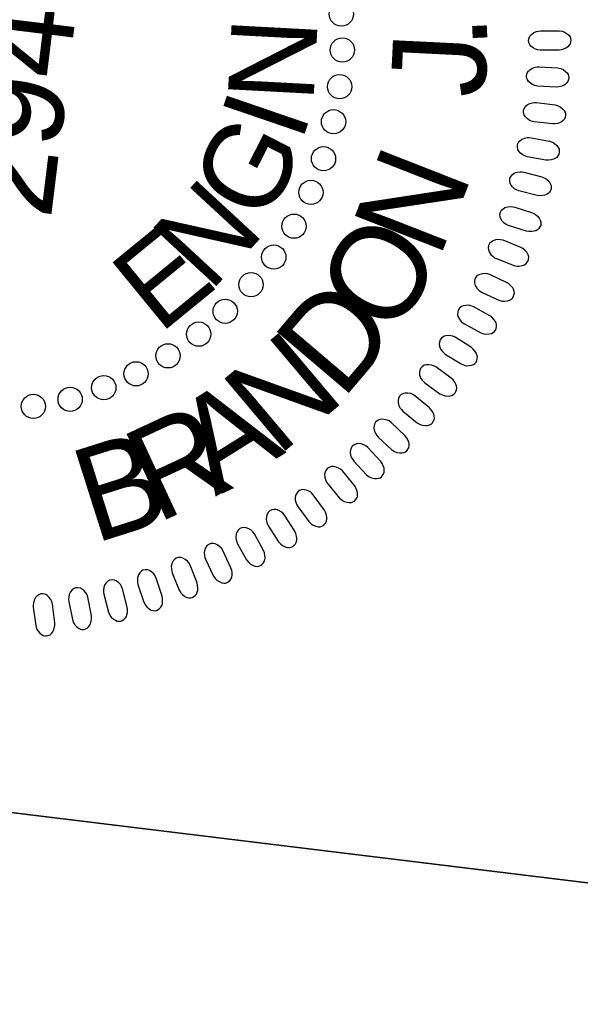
# Model space of a CAD drawing. Extents: x 480344 to 482186, y 488805 to 491553.
# Drawn here: x 480927.1 to 480964.2, y 490365.2 to 490429.6 of the extents above; entities that cross this region are included whole.
import ezdxf

# ---------------------------------------------------------------- set-up
doc = ezdxf.new("R2010")
doc.units = 0
for name, color, linetype in [('Sheet Layout Plan Border', 7, 'Continuous'), ('Sheet PE Seal Cell', 7, 'Continuous'), ('Sheet Plan CELL', 7, 'Continuous')]:
    doc.layers.add(name, color=color, linetype=linetype)

msp = doc.modelspace()

# ---------------------------------------------------------------- linework, layer by layer
at = {"layer": 'Sheet Layout Plan Border'}
msp.add_lwpolyline([(481703.226, 488995.253), (481861.691, 490292.688), (481782.266, 490302.389), (481802.944, 490471.693), (481574.795, 490460.718), (481089.788, 490519.955), (481007.711, 490529.98), (480988.134, 490369.7), (480815.851, 490390.73), (480660.971, 489122.552)], close=True, dxfattribs=at)
at = {"layer": 'Sheet PE Seal Cell'}
for points in [[(480961.54, 490428.859), (480962.767, 490428.864), (480962.986, 490428.827), (480963.127, 490428.776), (480963.297, 490428.664), (480963.407, 490428.567), (480963.487, 490428.455), (480963.527, 490428.351), (480963.547, 490428.239), (480963.528, 490428.127), (480963.499, 490428.007), (480963.439, 490427.902), (480963.34, 490427.797), (480963.26, 490427.737), (480963.11, 490427.669), (480962.931, 490427.608), (480962.772, 490427.586), (480961.515, 490427.573), (480961.346, 490427.595), (480961.206, 490427.64), (480961.046, 490427.729), (480960.906, 490427.84), (480960.826, 490427.937), (480960.765, 490428.094), (480960.745, 490428.244), (480960.785, 490428.393), (480960.834, 490428.498), (480960.933, 490428.625), (480961.102, 490428.745), (480961.282, 490428.813), (480961.411, 490428.843)], [(480961.446, 490426.487), (480962.671, 490426.415), (480962.888, 490426.365), (480963.024, 490426.305), (480963.187, 490426.182), (480963.291, 490426.079), (480963.363, 490425.962), (480963.397, 490425.856), (480963.41, 490425.742), (480963.383, 490425.632), (480963.346, 490425.514), (480963.281, 490425.413), (480963.175, 490425.314), (480963.092, 490425.26), (480962.938, 490425.201), (480962.756, 490425.152), (480962.595, 490425.139), (480961.34, 490425.206), (480961.172, 490425.238), (480961.036, 490425.292), (480960.882, 490425.391), (480960.749, 490425.51), (480960.675, 490425.612), (480960.624, 490425.772), (480960.614, 490425.923), (480960.662, 490426.07), (480960.718, 490426.171), (480960.825, 490426.292), (480961.002, 490426.402), (480961.185, 490426.458), (480961.316, 490426.481)], [(480961.28, 490424.123), (480962.498, 490423.974), (480962.711, 490423.91), (480962.844, 490423.841), (480962.998, 490423.709), (480963.096, 490423.599), (480963.161, 490423.478), (480963.188, 490423.37), (480963.194, 490423.256), (480963.161, 490423.147), (480963.116, 490423.032), (480963.045, 490422.935), (480962.932, 490422.844), (480962.846, 490422.794), (480962.689, 490422.745), (480962.504, 490422.708), (480962.343, 490422.705), (480961.095, 490422.85), (480960.929, 490422.893), (480960.796, 490422.955), (480960.648, 490423.063), (480960.524, 490423.191), (480960.456, 490423.298), (480960.416, 490423.461), (480960.414, 490423.612), (480960.472, 490423.755), (480960.534, 490423.853), (480960.648, 490423.968), (480960.831, 490424.065), (480961.018, 490424.11), (480961.15, 490424.123)], [(480960.924, 490421.796), (480962.13, 490421.57), (480962.338, 490421.493), (480962.466, 490421.417), (480962.613, 490421.275), (480962.703, 490421.16), (480962.76, 490421.035), (480962.781, 490420.924), (480962.779, 490420.81), (480962.739, 490420.704), (480962.688, 490420.592), (480962.61, 490420.5), (480962.492, 490420.416), (480962.403, 490420.371), (480962.243, 490420.333), (480962.056, 490420.307), (480961.895, 490420.314), (480960.659, 490420.537), (480960.496, 490420.591), (480960.367, 490420.661), (480960.227, 490420.778), (480960.11, 490420.913), (480960.049, 490421.024), (480960.019, 490421.189), (480960.028, 490421.34), (480960.094, 490421.48), (480960.162, 490421.573), (480960.283, 490421.68), (480960.472, 490421.766), (480960.662, 490421.8), (480960.794, 490421.805)], [(480960.447, 490419.52), (480961.636, 490419.219), (480961.84, 490419.129), (480961.963, 490419.044), (480962.1, 490418.894), (480962.182, 490418.773), (480962.232, 490418.644), (480962.245, 490418.533), (480962.236, 490418.419), (480962.19, 490418.316), (480962.132, 490418.207), (480962.048, 490418.12), (480961.925, 490418.044), (480961.833, 490418.005), (480961.672, 490417.977), (480961.483, 490417.962), (480961.323, 490417.98), (480960.103, 490418.28), (480959.945, 490418.344), (480959.82, 490418.422), (480959.687, 490418.547), (480959.579, 490418.69), (480959.526, 490418.804), (480959.506, 490418.971), (480959.524, 490419.121), (480959.599, 490419.256), (480959.673, 490419.345), (480959.8, 490419.444), (480959.994, 490419.518), (480960.185, 490419.54), (480960.318, 490419.537)], [(480959.836, 490417.21), (480961.005, 490416.836), (480961.202, 490416.733), (480961.319, 490416.641), (480961.447, 490416.482), (480961.521, 490416.356), (480961.563, 490416.225), (480961.569, 490416.113), (480961.553, 490416), (480961.5, 490415.9), (480961.435, 490415.795), (480961.346, 490415.714), (480961.22, 490415.645), (480961.125, 490415.612), (480960.962, 490415.593), (480960.773, 490415.591), (480960.614, 490415.619), (480959.416, 490415.995), (480959.261, 490416.069), (480959.142, 490416.154), (480959.017, 490416.288), (480958.918, 490416.437), (480958.872, 490416.554), (480958.863, 490416.722), (480958.89, 490416.871), (480958.974, 490417), (480959.053, 490417.085), (480959.186, 490417.176), (480959.384, 490417.237), (480959.576, 490417.247), (480959.708, 490417.236)], [(480958.628, 490413.81), (480959.77, 490413.363), (480959.987, 490413.318), (480960.137, 490413.315), (480960.336, 490413.358), (480960.473, 490413.408), (480960.588, 490413.484), (480960.664, 490413.566), (480960.723, 490413.664), (480960.745, 490413.775), (480960.761, 490413.898), (480960.744, 490414.017), (480960.689, 490414.15), (480960.637, 490414.235), (480960.522, 490414.352), (480960.376, 490414.474), (480960.236, 490414.553), (480959.069, 490415.018), (480958.902, 490415.059), (480958.756, 490415.068), (480958.575, 490415.042), (480958.404, 490414.989), (480958.294, 490414.927), (480958.181, 490414.803), (480958.108, 490414.671), (480958.091, 490414.517), (480958.099, 490414.402), (480958.145, 490414.247), (480958.26, 490414.074), (480958.403, 490413.946), (480958.512, 490413.871)], [(480957.677, 490411.576), (480958.789, 490411.058), (480959.004, 490410.999), (480959.152, 490410.987), (480959.353, 490411.017), (480959.494, 490411.059), (480959.614, 490411.128), (480959.693, 490411.205), (480959.759, 490411.298), (480959.788, 490411.408), (480959.812, 490411.53), (480959.802, 490411.65), (480959.755, 490411.787), (480959.708, 490411.874), (480959.601, 490411.999), (480959.464, 490412.128), (480959.329, 490412.217), (480958.193, 490412.754), (480958.029, 490412.805), (480957.884, 490412.823), (480957.702, 490412.809), (480957.528, 490412.767), (480957.414, 490412.712), (480957.294, 490412.596), (480957.212, 490412.468), (480957.185, 490412.316), (480957.187, 490412.2), (480957.223, 490412.043), (480957.326, 490411.863), (480957.461, 490411.726), (480957.566, 490411.644)], [(480956.513, 490409.493), (480957.591, 490408.906), (480957.801, 490408.834), (480957.949, 490408.812), (480958.152, 490408.83), (480958.294, 490408.863), (480958.418, 490408.924), (480958.503, 490408.996), (480958.575, 490409.085), (480958.61, 490409.193), (480958.641, 490409.313), (480958.64, 490409.433), (480958.601, 490409.572), (480958.56, 490409.663), (480958.461, 490409.794), (480958.332, 490409.932), (480958.203, 490410.029), (480957.102, 490410.636), (480956.943, 490410.698), (480956.799, 490410.724), (480956.616, 490410.722), (480956.44, 490410.691), (480956.323, 490410.643), (480956.195, 490410.534), (480956.106, 490410.412), (480956.07, 490410.262), (480956.064, 490410.146), (480956.09, 490409.987), (480956.182, 490409.801), (480956.308, 490409.656), (480956.407, 490409.568)], [(480955.255, 490407.503), (480956.293, 490406.85), (480956.499, 490406.765), (480956.644, 490406.734), (480956.848, 490406.739), (480956.993, 490406.763), (480957.12, 490406.815), (480957.209, 490406.882), (480957.286, 490406.967), (480957.328, 490407.073), (480957.367, 490407.19), (480957.372, 490407.31), (480957.343, 490407.452), (480957.308, 490407.545), (480957.217, 490407.682), (480957.097, 490407.828), (480956.974, 490407.932), (480955.914, 490408.608), (480955.758, 490408.679), (480955.617, 490408.715), (480955.434, 490408.725), (480955.256, 490408.704), (480955.137, 490408.664), (480955.003, 490408.563), (480954.906, 490408.447), (480954.86, 490408.299), (480954.847, 490408.184), (480954.863, 490408.023), (480954.943, 490407.832), (480955.06, 490407.679), (480955.153, 490407.585)], [(480953.907, 490405.593), (480954.902, 490404.876), (480955.102, 490404.778), (480955.246, 490404.738), (480955.449, 490404.73), (480955.595, 490404.745), (480955.725, 490404.789), (480955.819, 490404.851), (480955.9, 490404.931), (480955.949, 490405.033), (480955.995, 490405.147), (480956.008, 490405.267), (480955.988, 490405.41), (480955.959, 490405.505), (480955.876, 490405.648), (480955.766, 490405.801), (480955.649, 490405.913), (480954.634, 490406.653), (480954.484, 490406.734), (480954.344, 490406.779), (480954.162, 490406.8), (480953.984, 490406.791), (480953.862, 490406.759), (480953.722, 490406.666), (480953.618, 490406.556), (480953.563, 490406.412), (480953.542, 490406.298), (480953.549, 490406.137), (480953.617, 490405.941), (480953.723, 490405.781), (480953.81, 490405.681)], [(480952.455, 490403.738), (480953.404, 490402.959), (480953.597, 490402.849), (480953.738, 490402.8), (480953.941, 490402.779), (480954.087, 490402.785), (480954.219, 490402.821), (480954.317, 490402.876), (480954.403, 490402.951), (480954.459, 490403.05), (480954.512, 490403.161), (480954.532, 490403.28), (480954.521, 490403.424), (480954.498, 490403.522), (480954.425, 490403.668), (480954.324, 490403.828), (480954.215, 490403.947), (480953.248, 490404.75), (480953.103, 490404.84), (480952.967, 490404.894), (480952.786, 490404.926), (480952.607, 490404.928), (480952.484, 490404.903), (480952.338, 490404.821), (480952.228, 490404.717), (480952.164, 490404.576), (480952.136, 490404.463), (480952.132, 490404.302), (480952.187, 490404.103), (480952.284, 490403.936), (480952.365, 490403.831)], [(480950.822, 490402.021), (480951.72, 490401.185), (480951.906, 490401.063), (480952.044, 490401.006), (480952.244, 490400.972), (480952.391, 490400.968), (480952.526, 490400.996), (480952.626, 490401.045), (480952.717, 490401.114), (480952.779, 490401.209), (480952.838, 490401.318), (480952.867, 490401.435), (480952.864, 490401.579), (480952.847, 490401.677), (480952.783, 490401.828), (480952.693, 490401.994), (480952.592, 490402.12), (480951.677, 490402.982), (480951.538, 490403.081), (480951.405, 490403.143), (480951.228, 490403.187), (480951.049, 490403.201), (480950.924, 490403.183), (480950.773, 490403.11), (480950.656, 490403.013), (480950.584, 490402.876), (480950.549, 490402.766), (480950.535, 490402.605), (480950.578, 490402.403), (480950.664, 490402.23), (480950.738, 490402.12)], [(480949.216, 490400.423), (480950.059, 490399.532), (480950.238, 490399.398), (480950.371, 490399.332), (480950.569, 490399.287), (480950.716, 490399.274), (480950.852, 490399.293), (480950.955, 490399.335), (480951.051, 490399.398), (480951.117, 490399.489), (480951.184, 490399.594), (480951.219, 490399.709), (480951.226, 490399.854), (480951.215, 490399.953), (480951.161, 490400.108), (480951.082, 490400.279), (480950.988, 490400.411), (480950.129, 490401.328), (480949.997, 490401.436), (480949.867, 490401.506), (480949.693, 490401.561), (480949.516, 490401.585), (480949.39, 490401.576), (480949.235, 490401.512), (480949.113, 490401.423), (480949.032, 490401.292), (480948.99, 490401.183), (480948.966, 490401.024), (480948.996, 490400.819), (480949.071, 490400.641), (480949.138, 490400.527)], [(480947.492, 490398.931), (480948.278, 490397.989), (480948.447, 490397.844), (480948.577, 490397.771), (480948.771, 490397.712), (480948.917, 490397.69), (480949.054, 490397.7), (480949.159, 490397.737), (480949.258, 490397.793), (480949.331, 490397.88), (480949.404, 490397.98), (480949.447, 490398.093), (480949.463, 490398.237), (480949.458, 490398.336), (480949.414, 490398.495), (480949.345, 490398.67), (480949.26, 490398.808), (480948.461, 490399.777), (480948.335, 490399.893), (480948.211, 490399.972), (480948.04, 490400.037), (480947.865, 490400.072), (480947.739, 490400.071), (480947.58, 490400.017), (480947.452, 490399.936), (480947.363, 490399.81), (480947.315, 490399.704), (480947.28, 490399.547), (480947.298, 490399.34), (480947.361, 490399.158), (480947.421, 490399.04)], [(480945.517, 490397.424), (480946.242, 490396.434), (480946.401, 490396.28), (480946.526, 490396.198), (480946.717, 490396.127), (480946.86, 490396.096), (480946.998, 490396.098), (480947.106, 490396.127), (480947.208, 490396.178), (480947.286, 490396.26), (480947.365, 490396.355), (480947.414, 490396.465), (480947.44, 490396.608), (480947.441, 490396.707), (480947.407, 490396.868), (480947.349, 490397.048), (480947.273, 490397.19), (480946.537, 490398.208), (480946.418, 490398.332), (480946.299, 490398.417), (480946.133, 490398.493), (480945.96, 490398.54), (480945.835, 490398.546), (480945.672, 490398.502), (480945.54, 490398.43), (480945.443, 490398.309), (480945.388, 490398.207), (480945.344, 490398.052), (480945.348, 490397.844), (480945.4, 490397.659), (480945.453, 490397.538)], [(480943.576, 490396.14), (480944.238, 490395.106), (480944.387, 490394.942), (480944.506, 490394.852), (480944.692, 490394.77), (480944.833, 490394.73), (480944.971, 490394.723), (480945.08, 490394.746), (480945.186, 490394.79), (480945.269, 490394.867), (480945.354, 490394.957), (480945.41, 490395.063), (480945.444, 490395.204), (480945.451, 490395.303), (480945.427, 490395.466), (480945.381, 490395.649), (480945.314, 490395.795), (480944.643, 490396.858), (480944.533, 490396.989), (480944.419, 490397.082), (480944.258, 490397.168), (480944.088, 490397.226), (480943.964, 490397.24), (480943.799, 490397.206), (480943.662, 490397.142), (480943.558, 490397.028), (480943.497, 490396.929), (480943.443, 490396.777), (480943.434, 490396.57), (480943.474, 490396.382), (480943.519, 490396.257)], [(480941.538, 490394.975), (480942.134, 490393.902), (480942.273, 490393.728), (480942.386, 490393.631), (480942.567, 490393.537), (480942.705, 490393.489), (480942.842, 490393.474), (480942.952, 490393.489), (480943.061, 490393.526), (480943.148, 490393.598), (480943.239, 490393.682), (480943.301, 490393.785), (480943.344, 490393.923), (480943.358, 490394.022), (480943.344, 490394.186), (480943.309, 490394.371), (480943.252, 490394.522), (480942.649, 490395.624), (480942.547, 490395.762), (480942.439, 490395.862), (480942.284, 490395.958), (480942.118, 490396.026), (480941.994, 490396.049), (480941.828, 490396.025), (480941.687, 490395.969), (480941.576, 490395.862), (480941.509, 490395.768), (480941.446, 490395.619), (480941.424, 490395.413), (480941.452, 490395.223), (480941.489, 490395.095)], [(480939.423, 490393.947), (480939.95, 490392.839), (480940.078, 490392.657), (480940.185, 490392.553), (480940.359, 490392.448), (480940.494, 490392.391), (480940.63, 490392.367), (480940.741, 490392.376), (480940.851, 490392.406), (480940.943, 490392.472), (480941.039, 490392.551), (480941.108, 490392.649), (480941.159, 490392.784), (480941.179, 490392.882), (480941.176, 490393.046), (480941.152, 490393.234), (480941.105, 490393.387), (480940.572, 490394.526), (480940.479, 490394.669), (480940.378, 490394.776), (480940.229, 490394.882), (480940.068, 490394.96), (480939.945, 490394.99), (480939.778, 490394.977), (480939.634, 490394.931), (480939.517, 490394.831), (480939.444, 490394.741), (480939.371, 490394.596), (480939.336, 490394.391), (480939.353, 490394.2), (480939.381, 490394.07)], [(480937.224, 490393.051), (480937.68, 490391.912), (480937.796, 490391.722), (480937.896, 490391.612), (480938.063, 490391.496), (480938.195, 490391.43), (480938.328, 490391.398), (480938.44, 490391.4), (480938.552, 490391.423), (480938.648, 490391.484), (480938.748, 490391.556), (480938.823, 490391.65), (480938.883, 490391.782), (480938.909, 490391.878), (480938.916, 490392.042), (480938.905, 490392.231), (480938.867, 490392.387), (480938.407, 490393.557), (480938.322, 490393.706), (480938.228, 490393.818), (480938.086, 490393.933), (480937.931, 490394.021), (480937.81, 490394.059), (480937.643, 490394.056), (480937.496, 490394.019), (480937.372, 490393.926), (480937.294, 490393.841), (480937.213, 490393.702), (480937.165, 490393.5), (480937.169, 490393.308), (480937.189, 490393.177)], [(480934.964, 490392.272), (480935.348, 490391.106), (480935.452, 490390.91), (480935.545, 490390.793), (480935.705, 490390.668), (480935.831, 490390.593), (480935.963, 490390.553), (480936.074, 490390.548), (480936.187, 490390.564), (480936.287, 490390.618), (480936.392, 490390.684), (480936.472, 490390.773), (480936.54, 490390.901), (480936.573, 490390.995), (480936.59, 490391.158), (480936.59, 490391.348), (480936.562, 490391.506), (480936.176, 490392.702), (480936.101, 490392.856), (480936.016, 490392.975), (480935.881, 490393.098), (480935.731, 490393.196), (480935.613, 490393.241), (480935.445, 490393.249), (480935.296, 490393.221), (480935.168, 490393.136), (480935.083, 490393.056), (480934.994, 490392.922), (480934.934, 490392.724), (480934.925, 490392.532), (480934.938, 490392.4)], [(480932.712, 490391.641), (480933.021, 490390.454), (480933.113, 490390.25), (480933.198, 490390.128), (480933.35, 490389.993), (480933.472, 490389.911), (480933.6, 490389.862), (480933.711, 490389.85), (480933.825, 490389.859), (480933.928, 490389.907), (480934.036, 490389.966), (480934.122, 490390.049), (480934.198, 490390.173), (480934.236, 490390.265), (480934.264, 490390.427), (480934.276, 490390.616), (480934.258, 490390.776), (480933.948, 490391.994), (480933.884, 490392.152), (480933.805, 490392.276), (480933.678, 490392.407), (480933.534, 490392.514), (480933.42, 490392.567), (480933.253, 490392.586), (480933.103, 490392.567), (480932.969, 490392.491), (480932.88, 490392.416), (480932.782, 490392.288), (480932.71, 490392.093), (480932.689, 490391.902), (480932.694, 490391.769)], [(480928.053, 490390.787), (480928.211, 490389.57), (480928.276, 490389.358), (480928.346, 490389.225), (480928.479, 490389.072), (480928.59, 490388.975), (480928.711, 490388.911), (480928.82, 490388.885), (480928.934, 490388.88), (480929.042, 490388.914), (480929.157, 490388.959), (480929.253, 490389.032), (480929.344, 490389.145), (480929.394, 490389.231), (480929.441, 490389.388), (480929.477, 490389.574), (480929.478, 490389.735), (480929.324, 490390.982), (480929.28, 490391.148), (480929.217, 490391.28), (480929.107, 490391.426), (480928.978, 490391.551), (480928.872, 490391.617), (480928.708, 490391.656), (480928.557, 490391.657), (480928.414, 490391.598), (480928.317, 490391.535), (480928.203, 490391.42), (480928.107, 490391.236), (480928.063, 490391.049), (480928.051, 490390.917)], [(480930.399, 490391.159), (480930.633, 490389.955), (480930.712, 490389.746), (480930.789, 490389.619), (480930.932, 490389.474), (480931.049, 490389.385), (480931.174, 490389.328), (480931.284, 490389.309), (480931.398, 490389.311), (480931.504, 490389.352), (480931.616, 490389.404), (480931.707, 490389.483), (480931.79, 490389.601), (480931.835, 490389.69), (480931.872, 490389.85), (480931.896, 490390.038), (480931.888, 490390.199), (480931.655, 490391.434), (480931.6, 490391.596), (480931.53, 490391.724), (480931.411, 490391.863), (480931.275, 490391.979), (480931.164, 490392.039), (480930.998, 490392.068), (480930.848, 490392.059), (480930.709, 490391.991), (480930.615, 490391.922), (480930.51, 490391.8), (480930.425, 490391.611), (480930.393, 490391.422), (480930.389, 490391.289)]]:
    msp.add_lwpolyline(points, close=True, dxfattribs=at)
for centre in [(480948.386, 490429.969), (480948.456, 490427.594), (480948.279, 490425.169), (480947.875, 490422.852), (480947.214, 490420.406), (480946.38, 490418.182), (480945.264, 490415.952), (480943.93, 490413.909), (480942.423, 490412.088), (480940.723, 490410.331), (480938.973, 490408.82), (480936.95, 490407.383), (480934.839, 490406.198), (480932.708, 490405.281), (480930.486, 490404.51), (480928.061, 490404.045)]:
    msp.add_circle(centre, 0.801, dxfattribs=at)
at = {"layer": 'Sheet Plan CELL'}
msp.add_line((480815.851, 490390.73), (480964.808, 490372.549), dxfattribs=at)
msp.add_lwpolyline([(480853.149, 490386.174), (480865.278, 490485.486), (480976.961, 490471.846), (480964.808, 490372.549)], close=True, dxfattribs=at)

# ---------------------------------------------------------------- texts
at = {"layer": 'Sheet PE Seal Cell'}
for s, height, rotation, p in [('29470', 6.2363, 83.01787, (480929.202, 490416.34)), ('N', 5.669, 86.94089, (480946.543, 490424.076)), ('.', 6.236, 92.67422, (480958.065, 490427.666)), ('J', 6.236, 87.18222, (480957.853, 490424.387)), ('I', 5.669, 71.06129, (480945.74, 490421.4)), ('G', 5.669, 63.12149, (480943.38, 490416.018)), ('N', 6.236, 68.58702, (480954.845, 490413.722)), ('N', 5.669, 47.2419, (480939.711, 490411.535)), ('E', 5.669, 39.3021, (480936.398, 490408.782)), ('O', 6.236, 58.48717, (480951.818, 490408.499)), ('D', 6.236, 49.61894, (480948.439, 490404.412)), ('N', 6.236, 40.12926, (480944.173, 490400.672)), ('A', 6.236, 32.01808, (480940.08, 490398.07)), ('R', 6.236, 24.90124, (480936.216, 490396.283)), ('B', 6.236, 17.62621, (480932.069, 490394.965))]:
    msp.add_text(s, height=height, rotation=rotation, dxfattribs=at).set_placement(p)

doc.saveas('drawing.dxf')
